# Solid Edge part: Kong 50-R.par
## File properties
Title: Kong 50/R 50x38 Cm
Author: DESYS
Template: Normal.par
Last saved by: s.pallini
Revision: 17
Application: Solid Edge
Tipo di contenuto documento: 0
Precisione: 0,990
Document Number: 8051/R
Revision: 0
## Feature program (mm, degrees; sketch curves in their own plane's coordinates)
thicken "Assegnare_spessore_2"  Distance1 = 10 mm
thicken "Assegnare_spessore_1"  Distance1 = 10 mm
fillet "Rotondo_1" radius 30
fillet "Rotondo_2" radius 5
fillet "Rotondo_3" radius 5
sketch for "unnamed Cutout 1" plane through (0, 0, 0) normal (0, 0, 1) x-axis (1, 0, 0)
  circle centre (0, 0) radius 25
extrude "unnamed Cutout 1" cut through
sketch for "ProtrusioneEstrusa_1" plane through (0, 0, 15) normal (0, 0, 1) x-axis (1, 0, 0)
extrude "ProtrusioneEstrusa_1" add  Profile_Plane1_Distance = 15 mm
fillet "Rotondo_4" radius 10
sketch for "ExtrudedCutout_2" #1 plane through (0.4335, 0, 15) normal (0, 0, -1) x-axis (0, -1, 0)
sketch for "ExtrudedCutout_2" #2 plane through (0.4335, 0, 15) normal (0, 0, -1) x-axis (0, -1, 0)
sketch for "ExtrudedCutout_2" #3 plane through (0.4335, 0, 15) normal (0, 0, -1) x-axis (0, -1, 0)
extrude "ExtrudedCutout_2" cut finite 15 along -normal
fillet "Rotondo_5" radius 5
sketch for "ExtrudedProtrusion_2" plane through (0.1205, -0.5914, 108) normal (0, 0, -1) x-axis (0, 1, 0)
extrude "ExtrudedProtrusion_2" add finite 300.8906 along +normal  Profile_Plane1_Distance = 93 mm; Treatment1_DraftAngle = 5 deg
sketch for "Foro_1" plane through (0, 0, 0) normal (0, 0, 1) x-axis (1, 0, 0)
  hole centre (138, 0) bore radius 17.5
hole "Foro_1" diameter 35 through
sketch for "ExtrudedCutout_3" plane through (0, 0, 0) normal (0, 0, 1) x-axis (1, 0, 0)
  circle centre (145, 0) radius 37.5
  dimension (linear) = 145
extrude "ExtrudedCutout_3" cut finite 95 along +normal
fillet "Rotondo_7" radius 3
fillet "Rotondo_8" radius 6
fillet "Rotondo_9" radius 8
Other named dimensions: "CurveByTable_2": Tolerance = 1 mm | "CurveByTable_3": Tolerance = 1 mm | "CurveByTable_4": Tolerance = 1 mm
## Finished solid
Body 1: solid body, 51 faces, 98 edges, 48 vertices.
  Faces by surface: blend 30, plane 7, cylinder 6, torus 3, swept 2, cone 1, offset 1, spline 1
  Edges by curve: intersection 52, circle 39, line 6, ellipse 1
Body 2: sheet body, 1 face, 4 edges, 4 vertices.
  Faces by surface: spline 1
  Edges by curve: spline 4
Bounding box of the edges (mm; curved faces can reach further): 395.512 x 505.000 x 140.000, from (-184.853, -240, 15) to (210.6595, 265, 155).
Cylindrical faces by radius (mm): R6 x2, R17.5 x1, R25 x1, R35 x1, R37.5 x1
Conical faces (half-angle, radius in mm at the cone's reference point): 5 deg R100 x1
Toroidal faces (ring radius, tube radius in mm): R20.5 r3 x1, R30 r5 x1, R94.502 r6 x1
Planar faces by outward normal: +z 1, -z 4, oblique 2
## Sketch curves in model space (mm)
arc centre (-4.1484, 0, 307.5549) radius 287.5849 from (-180, 0, 80) through (23.028, 0, 21.257) to (200, 0, 105)
circle centre (0, 0, 20) radius 25
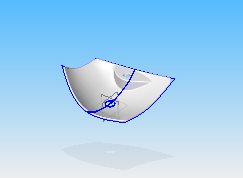
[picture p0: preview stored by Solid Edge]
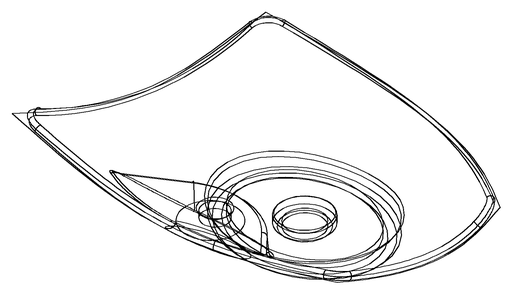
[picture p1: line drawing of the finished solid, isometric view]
